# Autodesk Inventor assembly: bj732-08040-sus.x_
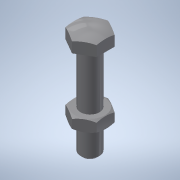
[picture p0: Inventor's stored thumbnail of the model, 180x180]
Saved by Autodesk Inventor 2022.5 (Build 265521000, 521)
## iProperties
Part Number: bj732-08040-sus.x_
Material: 一般
Document SubType Name: Assembly
Designer: ImaoCorp
Sending System: SOLIDWORKS 2017-2017317
MC: AMD64
MC_MODEL: Intel64 Family 6 Model 60 Stepping 3, GenuineIntel
OS: Windows_NT
FRU: Parasolid Version 29.0, build 201,  4-17-2017
FORMAT: text
GUISE: transmit
KEY: bj732-08040-sus
FILE: bj732-08040-sus.x_t
DATE: Fri Mar 15 10:10:56 2019
Author: ImaoCorp
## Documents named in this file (3)
- X:\14_SW2022-Inv2022\00_全2023-1023新製品(TCC)まで\b\bj732-08040-sus\BJ732-08040-SUS.iam
- X:\14_SW2022-Inv2022\00_全2023-1023新製品(TCC)まで\b\bj732-08040-sus\bj732-08040-sus_01.ipt
- X:\14_SW2022-Inv2022\00_全2023-1023新製品(TCC)まで\b\bj732-08040-sus\bj732-08040-sus_02.ipt
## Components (2 placed, 2 different names)
1. bj732-08040-sus_01
2. bj732-08040-sus_02
